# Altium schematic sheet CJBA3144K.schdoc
size 127 x 101 mm
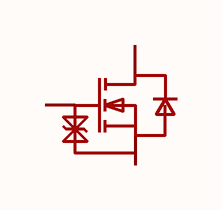
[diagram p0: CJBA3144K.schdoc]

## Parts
Q?  cjba3144k  [DFN1006-3L_L1.0-W0.6-P0.35-BL]  (value not drawn)

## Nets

Not connected (* = marked no-connect by the designer): Q? 1(G) 2(S) 3(D)

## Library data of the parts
Q? = cjba3144k: 数量:1个N沟道;漏源电压(Vdss):30V;连续漏极电流(Id):600mA;导通电阻(RDS(on)):600mΩ@2.5V;耗散功率(Pd):275mW;阈值电压(Vgs(th)):1.5V;; Manufacturer: CJ(江苏长电/长晶); AddInBom: yes; ModelId: 39f1344397464ba59ca0eae50e55ba71; ModelTransform: 23.622,39.37,0,0,0,0,0,0,0; Number: 1个N沟道; Drain to Source Voltage: 30V; Current - Continuous Drain(Id): 600mA; Pd - Power Dissipation: 275mW; Gate Threshold Voltage (Vgs(th)): 1.5V; Gate Charge(Qg): 60nC@4.5V; Input Capacitance(Ciss): 42pF; Reverse Transfer Capacitance (Crss@Vds): 4.7pF; Type: N沟道; Output Capacitance(Coss): 9pF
